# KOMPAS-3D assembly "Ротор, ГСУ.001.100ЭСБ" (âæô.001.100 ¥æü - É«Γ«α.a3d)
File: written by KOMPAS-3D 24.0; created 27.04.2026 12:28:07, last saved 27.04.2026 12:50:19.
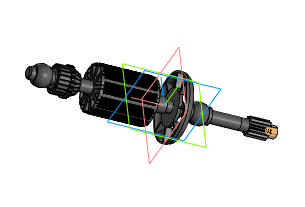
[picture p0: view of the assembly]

Document properties: Автор: USG_411; Полное имя файла: C:\Users\USG_411.STUD\Desktop\ГМ2704_411-23\Двигатель мясорубки\ГСУ.001.100 ЭСБ - Ротор.a3d

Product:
- Component [detail]: Звёздочка  | designation ГСУ.001.101  | qty 1  | pos. 1  | Масса: 0.070568; Автор: USG_411; source file: ГСУ.001.101 ЭМД - Звёздочка.m3d
- Component [detail]: Вал ротора  | designation ГСУ.001.102  | qty 1  | pos. 2  | Масса: 0.060181; Автор: USG_411; source file: ГСУ.001.102 ЭМД - Вал ротора.m3d
- Component [detail]: Шестерёнка  | designation ГСУ.001.103  | qty 1  | pos. 3  | Масса: 0.005595; Автор: USG_411; source file: ГСУ.001.103 ЭМД - Шестерёнка.m3d
- Component [detail]: Пропеллер  | designation ГСУ.001.104  | qty 1  | pos. 4  | Масса: 0.029778; Автор: USG_411; source file: ГСУ.001.104 ЭМД - Пропеллер.m3d
- Component [detail]: Коллектор  | designation ГСУ.001.105  | qty 1  | pos. 5  | Масса: 0.020234; Автор: USG_411; source file: ГСУ.001.105 ЭМД - Коллектор.m3d
- Component [detail]: Шайба  | designation ГСУ.001.106  | qty 2  | pos. 6  | Масса: 0.000703; Автор: USG_411; source file: ГСУ.001.106 ЭМД - Шайба.m3d
- Component [detail]: Втулка  | designation ГСУ.001.107  | qty 2  | pos. 7  | Масса: 0.007197; Автор: USG_411; source file: ГСУ.001.107 ЭМД - Втулка.m3d
- Component [detail]: Пластина  | designation ГСУ.001.108  | qty 10  | pos. 8  | Масса: 0.00167; Автор: USG_411; source file: ГСУ.001.108 ЭМД - Пластина.m3d
- Component [detail]: Пластина  | designation ГСУ.001.110  | qty 10  | pos. 9  | Масса: 0.002837; Автор: USG_411; source file: ГСУ.001.110 ЭМД - Пластина.m3d
- Component [standard]: Гайка М4-6H ГОСТ 15523-70  | qty 1  | Масса: 0.001183; Раздел спецификации: Стандартные изделия; Рассекать на разрезах: no
- Part/product: Ротор  | designation ГСУ.001.100ЭСБ
    Масса: 0.24841

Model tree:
1. Контекстная связь:1  (with: Эскиз:4, Грань.Элемент вращения:1, Ребро.Элемент вращения:1, Контекстная связь (ГСУ.001.103 Шестерёнка):1)
2. Массив по сетке:1  (2 pattern instances)
     Шаг 1 = 12; Угол раствора = 90
3. Массив по концентрической сетке:1  (with: Грань.Элемент выдавливания:1)  (10 pattern instances)
     Шаг 2 = 360
4. Массив по концентрической сетке:2  (with: Грань.Элемент выдавливания:1, Грань.Элемент вращения:1, Грань.Элемент выдавливания:4, Грань.Элемент выдавливания:2)  (labels: Грань.Элемент выдавливания:1.Экземпляр ( 2 ); Грань.Элемент выдавливания:1.Экземпляр ( 109, 1 ); Грань.Элемент выдавливания:2.Экземпляр ( 1, 10 ); Грань.Элемент выдавливания:1.Экземпляр ( 110, 1 ))  (10 pattern instances)
     Шаг 2 = 360; Расстояние = -38.2; Расстояние = 4; Расстояние = 2.5; Расстояние = 1.85; Расстояние = 10; Расстояние = -19; Расстояние = 4.5; Расстояние = 1

Referenced files in C:\Users\USG_411.STUD\Desktop\ГМ2704_411-23\Двигатель мясорубки\: ГСУ.001.101 ЭМД - Звёздочка.m3d, ГСУ.001.102 ЭМД - Вал ротора.m3d, ГСУ.001.103 ЭМД - Шестерёнка.m3d, ГСУ.001.104 ЭМД - Пропеллер.m3d, ГСУ.001.105 ЭМД - Коллектор.m3d, ГСУ.001.106 ЭМД - Шайба.m3d, ГСУ.001.107 ЭМД - Втулка.m3d, ГСУ.001.108 ЭМД - Пластина.m3d, ГСУ.001.110 ЭМД - Пластина.m3d
Referenced files in C:\Program Files\ASCON\KOMPAS-3D v21\Libs\PARTLib\DATA\vault\Methods\Kompas\3D\: PLib_Nut_OST92_900.m3d
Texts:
  Body Specification ( left align )
  Body Specificaton ( centered )
  ГСУ.001.101
  ГСУ.001.101 ЭМД
  ГСУ.001.102
  ГСУ.001.102 ЭМД
  ГСУ.001.103
  ГСУ.001.103 ЭМД
  ГСУ.001.104
  ГСУ.001.104 ЭМД
  ГСУ.001.105
  ГСУ.001.105 ЭМД
  ГСУ.001.106
  ГСУ.001.106 ЭМД
  ГСУ.001.107
  ГСУ.001.107 ЭМД
  ГСУ.001.108
  ГСУ.001.108 ЭМД
  ГСУ.001.110
  ГСУ.001.110 ЭМД
  Крепежное изделие ГОСТ
  Программные изделия  и базы данных
  ГСУ.001.100
  Точка начала. Х
  Точка начала. Y
  Точка начала. Z
  ГСУ.001.100 ЭСБ
  ГСУ.001.101 Звёздочка
  ГСУ.001.102 Вал ротора
  ГСУ.001.103 Шестерёнка
  ГСУ.001.104 Пропеллер
  ГСУ.001.105 Коллектор
  ГСУ.001.106 Шайба (1)
  ГСУ.001.107 Втулка (1)
  ГСУ.001.106 Шайба (2)
  ГСУ.001.107 Втулка (2)
  ГСУ.001.108 Пластина (1)
  ГСУ.001.108 Пластина (2)
  ГСУ.001.108 Пластина (3)
  ГСУ.001.108 Пластина (4)
  ГСУ.001.108 Пластина (5)
  ГСУ.001.108 Пластина (6)
  ГСУ.001.108 Пластина (7)
  ГСУ.001.108 Пластина (8)
  ГСУ.001.108 Пластина (9)
  ГСУ.001.108 Пластина (10)
  ГСУ.001.110 Пластина (1)
  ГСУ.001.110 Пластина (2)
  ГСУ.001.110 Пластина (3)
  ГСУ.001.110 Пластина (4)
  ГСУ.001.110 Пластина (5)
  ГСУ.001.110 Пластина (6)
  ГСУ.001.110 Пластина (7)
  ГСУ.001.110 Пластина (8)
  ГСУ.001.110 Пластина (9)
  ГСУ.001.110 Пластина (10)
  bcut1
  hole1
  hcut1
  hole2
  cut1
  Грань.Элемент выдавливания:2.Экземпляр ( 1, 4 )
  Грань.Элемент выдавливания:2.Экземпляр ( 1, 3 )
  Plane. Начало координат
